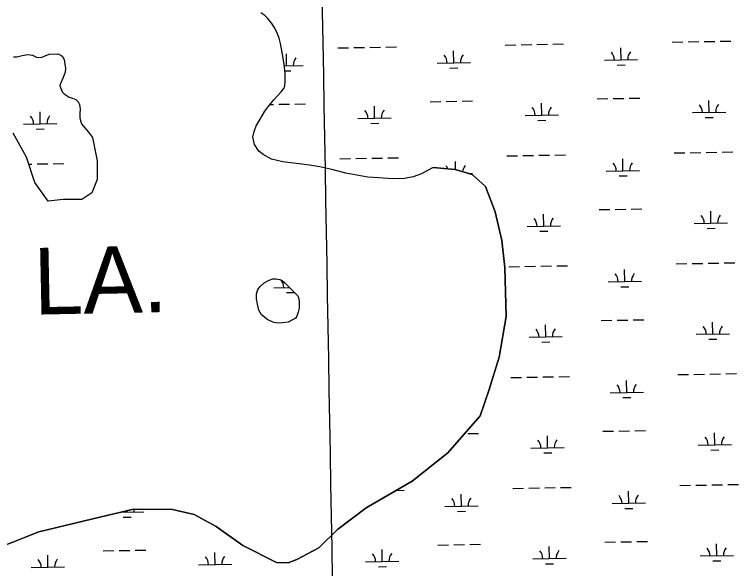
# Model space of a CAD drawing. Extents: x 3892998 to 3931244, y 278583 to 304547.
# Drawn here: x 3917313 to 3919486, y 298805 to 300467 of the extents above; entities that cross this region are included whole.
import ezdxf

# ---------------------------------------------------------------- set-up
doc = ezdxf.new("R2010")
doc.units = 0
for name, color, linetype in [('V-GRID-MAJR', 7, 'Continuous'), ('V-TOPO-GNAM-IDEN', 7, 'Continuous'), ('V-TOPO-SHOR', 7, 'Continuous'), ('V-WETL-SWMP', 7, 'Continuous')]:
    doc.layers.add(name, color=color, linetype=linetype)

msp = doc.modelspace()

# ---------------------------------------------------------------- linework, layer by layer
at = {"layer": 'V-GRID-MAJR'}
msp.add_spline([(3918519.216, 284383.145), (3918413.491, 290439.973), (3918307.7120000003, 296499.886), (3918201.934, 302559.792), (3918201.88, 302562.882)], degree=3, dxfattribs=at)
at = {"layer": 'V-TOPO-SHOR'}
for points in [[(3918570.412, 300008.11100000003), (3918552.9110000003, 299999.548), (3918534.8030000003, 299989.208), (3918509.971, 299980.115), (3918483.789, 299975.189), (3918448.3370000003, 299974.503), (3918406.176, 299976.846), (3918374.318, 299979.496), (3918307.485, 299991.16000000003), (3918265.399, 300002.016), (3918230.216, 300009.843), (3918198.577, 300014.867), (3918167.324, 300019.096), (3918142.199, 300022.08400000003), (3918119.2600000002, 300025.648), (3918084.47, 300033.076), (3918060.034, 300046.949), (3918047.055, 300057.556), (3918033.7600000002, 300077.27400000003), (3918028.796, 300098.903), (3918032.31, 300116.10000000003), (3918039.193, 300133.666), (3918050.256, 300153.57), (3918064.719, 300177.605), (3918076.344, 300193.744), (3918091.54, 300210.842), (3918113.529, 300234.81200000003), (3918121.74, 300245.239), (3918124.384, 300253.533), (3918126.282, 300266.982), (3918125.49, 300289.961), (3918122.367, 300318.303), (3918116.329, 300353.20900000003), (3918111.809, 300380.378), (3918107.394, 300396.653), (3918100.416, 300414.338), (3918092.429, 300429.655), (3918085.99, 300440.8), (3918074.04, 300455.755), (3918064.605, 300463.955), (3918053.1890000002, 300472.17100000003)], [(3917310.1890000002, 300340.018), (3917319.919, 300339.934), (3917336.6350000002, 300344.159), (3917353.345, 300347.786), (3917367.423, 300345.482), (3917379.481, 300339.422), (3917385.625, 300338.179), (3917395.562, 300339.28500000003), (3917405.329, 300343.371), (3917417.2830000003, 300348.23), (3917443.895, 300348.798), (3917452.798, 300344.947), (3917457.528, 300340.935), (3917462.812, 300331.957), (3917466.3570000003, 300305.517), (3917465.2660000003, 300294.01), (3917459.968, 300278.17), (3917452.486, 300262.548), (3917450.664, 300258.395), (3917449.623, 300252.84500000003), (3917456.0270000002, 300235.515), (3917462.728, 300229.69800000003), (3917477.931, 300219.641), (3917487.634, 300216.579), (3917497.722, 300212.32300000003), (3917504.219, 300205.714), (3917508.909, 300196.939), (3917510.381, 300183.424), (3917509.0810000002, 300170.726), (3917509.7630000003, 300157.617), (3917511.473, 300148.667), (3917514.772, 300139.703), (3917523.4110000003, 300128.31), (3917535.6040000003, 300114.705), (3917547.38, 300098.718)], [(3917547.38, 300098.718), (3917561.9560000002, 300027.729), (3917561.4790000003, 299972.052), (3917545.947, 299931.69), (3917515.403, 299911.703), (3917459.728, 299912.183), (3917414.129, 299907.511), (3917374.115, 299963.536), (3917349.46, 300039.677), (3917309.577, 300110.884)], [(3918570.412, 300008.11100000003), (3918636.169, 300002.485), (3918686.6520000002, 299986.867), (3918726.842, 299951.088), (3918756.558, 299874.905), (3918776.066, 299788.684), (3918785.4930000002, 299707.614), (3918789.296, 299560.787), (3918768.007, 299439.48600000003), (3918736.769, 299338.515), (3918710.808, 299262.811), (3918613.684, 299152.282), (3918506.653, 299067.14900000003), (3918369.298, 298987.339), (3918282.688, 298922.278), (3918226.534, 298867.08), (3918160.431, 298832.215), (3918135.0360000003, 298822.309), (3918099.605, 298822.612), (3917998.809, 298874.096), (3917918.304, 298930.468), (3917852.809, 298966.463), (3917787.14, 298982.212), (3917670.723, 298983.212), (3917548.988, 298953.886), (3917386.6720000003, 298914.784), (3917234.305, 298855.349)], [(3918148.057, 299550.928), (3918134.734, 299544.507), (3918118.275, 299541.878), (3918104.211, 299541.402), (3918091.356, 299543.297), (3918073.598, 299550.77400000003), (3918054.914, 299565.788), (3918046.72, 299580.116), (3918042.3200000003, 299598.175), (3918039.877, 299613.641), (3918039.421, 299629.487), (3918043.289, 299641.931), (3918050.494, 299650.78), (3918062.872, 299662.357), (3918078.187, 299670.146), (3918089.111, 299674.012), (3918098.225, 299674.529), (3918109.495, 299672.452), (3918116.989, 299668.82300000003), (3918125.049, 299662.021), (3918133.688, 299653.233), (3918141.339, 299645.05), (3918154.694, 299632.061), (3918163.921, 299622.675), (3918165.852, 299616.916), (3918167.548, 299606.803), (3918167.7830000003, 299588.18700000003), (3918166.7430000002, 299582.254), (3918164.691, 299573.955), (3918160.625, 299561.712), (3918156.417, 299555.808), (3918148.057, 299550.928)]]:
    msp.add_lwpolyline(points, dxfattribs=at)
at = {"layer": 'V-WETL-SWMP'}
for p, q in [((3918064.6040000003, 300463.954), (3918053.1890000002, 300472.17100000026)), ((3918074.039, 300455.754), (3918064.6040000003, 300463.954)), ((3918085.99, 300440.799), (3918074.039, 300455.754)), ((3918092.429, 300429.654), (3918085.99, 300440.799)), ((3918100.417, 300414.3380000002), (3918092.429, 300429.654)), ((3918107.394, 300396.6530000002), (3918100.417, 300414.3380000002)), ((3918111.809, 300380.377), (3918107.394, 300396.6530000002)), ((3918116.329, 300353.20900000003), (3918111.809, 300380.377)), ((3918785.654375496, 300375.7764404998), (3918817.649582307, 300376.33028264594)), ((3918833.647185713, 300376.6072037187), (3918865.642392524, 300377.1610458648)), ((3918881.639995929, 300377.4379669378), (3918913.63520274, 300377.99180908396)), ((3918929.6328061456, 300378.2687301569), (3918961.6280129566, 300378.82257230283)), ((3919287.487196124, 300384.46324686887), (3919319.482402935, 300385.017089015)), ((3919335.48000634, 300385.29401008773), (3919367.475213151, 300385.8478522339)), ((3919383.472816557, 300386.12477330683), (3919415.468023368, 300386.678615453)), ((3919431.465626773, 300386.955536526), (3919463.4608335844, 300387.5093786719)), ((3918122.366, 300318.304), (3918116.329, 300353.20900000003)), ((3918283.821554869, 300367.0896341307), (3918315.81676168, 300367.6434762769)), ((3918331.8143650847, 300367.9203973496), (3918363.8095718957, 300368.47423949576)), ((3918379.8071753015, 300368.75116056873), (3918411.8023821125, 300369.30500271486)), ((3918427.7999855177, 300369.58192378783), (3918459.795192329, 300370.1357659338)), ((3918631.96375196, 300322.3664295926), (3918631.340679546, 300358.3610372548)), ((3919133.796572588, 300331.0532359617), (3919133.1735001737, 300367.0478436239)), ((3918130.1309313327, 300313.67962322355), (3918129.507858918, 300349.67423088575)), ((3919083.804061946, 300330.18785760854), (3919183.7890832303, 300331.9186143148)), ((3918125.489, 300289.96), (3918122.366, 300318.304)), ((3918122.88933498, 300313.5542700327), (3918180.1234419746, 300314.54500157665)), ((3918581.9712413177, 300321.5010512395), (3918681.956262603, 300323.23180794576)), ((3919122.065443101, 300315.41685652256), (3919146.0618482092, 300315.83223813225)), ((3918124.5865718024, 300298.1503377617), (3918142.396206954, 300298.4586253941)), ((3918126.282, 300266.982), (3918125.489, 300289.96)), ((3918620.2326224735, 300306.7300501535), (3918644.2290275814, 300307.1454317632)), ((3918124.384, 300253.532), (3918126.282, 300266.982)), ((3918113.5300000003, 300234.813), (3918121.739, 300245.238)), ((3918121.739, 300245.238), (3918124.384, 300253.532)), ((3918091.541, 300210.842), (3918113.5300000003, 300234.813)), ((3918076.344, 300193.744), (3918091.541, 300210.842)), ((3918154.7173944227, 300198.6559260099), (3918186.7126012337, 300199.2097681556)), ((3918560.564594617, 300205.6812059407), (3918592.559801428, 300206.2350480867)), ((3918608.5574048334, 300206.5119691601), (3918640.552611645, 300207.0658113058)), ((3918656.5502150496, 300207.342732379), (3918688.5454218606, 300207.89657452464)), ((3918896.162029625, 300165.0534955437), (3918895.5389572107, 300201.0481032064)), ((3919062.3974152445, 300214.3680123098), (3919094.392622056, 300214.9218544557)), ((3919110.390225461, 300215.19877552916), (3919142.385432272, 300215.7526176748)), ((3919158.383035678, 300216.02953874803), (3919190.378242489, 300216.5833808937)), ((3919397.9948502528, 300173.74030191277), (3919397.3717778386, 300209.7349095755)), ((3918050.256, 300153.571), (3918064.72, 300177.606)), ((3918064.72, 300177.606), (3918076.344, 300193.744)), ((3918079.5533637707, 300197.35482462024), (3918090.7269808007, 300197.54824171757)), ((3918106.7245842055, 300197.825162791), (3918138.7197910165, 300198.3790049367)), ((3918394.3292089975, 300156.36668917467), (3918393.7061365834, 300192.36129683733)), ((3917390.6635677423, 300138.9930764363), (3917390.040495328, 300174.98768409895)), ((3918344.3366983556, 300155.50131082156), (3918444.3217196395, 300157.23206752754)), ((3918846.169518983, 300164.1881171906), (3918946.154540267, 300165.9188738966)), ((3919348.0023396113, 300172.87492355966), (3919447.9873608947, 300174.6056802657)), ((3919386.263720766, 300158.1039224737), (3919410.2601258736, 300158.5193040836)), ((3917340.6710571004, 300138.1276980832), (3917440.6560783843, 300139.85845478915)), ((3918032.31, 300116.10000000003), (3918039.194, 300133.665)), ((3918039.194, 300133.665), (3918050.256, 300153.571)), ((3918382.598079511, 300140.7303097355), (3918406.5944846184, 300141.14569134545)), ((3918884.430900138, 300149.4171161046), (3918908.4273052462, 300149.83249771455)), ((3917378.9324382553, 300123.3566969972), (3917402.928843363, 300123.7720786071)), ((3918028.796, 300098.90200000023), (3918032.31, 300116.10000000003)), ((3918033.759, 300077.27400000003), (3918028.796, 300098.90200000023)), ((3918047.056, 300057.556), (3918033.759, 300077.27400000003)), ((3918060.034, 300046.949), (3918047.056, 300057.556)), ((3918084.47, 300033.075), (3918060.034, 300046.949)), ((3919293.2449909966, 300051.8380773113), (3919325.2401978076, 300052.39191945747)), ((3919341.237801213, 300052.66884053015), (3919373.233008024, 300053.22268267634)), ((3919389.230611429, 300053.49960374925), (3919421.22581824, 300054.05344589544)), ((3919437.223421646, 300054.3303669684), (3919469.2186284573, 300054.8842091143)), ((3918119.259, 300025.647), (3918084.47, 300033.075)), ((3918142.2, 300022.08400000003), (3918119.259, 300025.64699999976)), ((3918289.579349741, 300034.46446457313), (3918321.574556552, 300035.0183067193)), ((3918337.5721599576, 300035.29522779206), (3918369.5673667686, 300035.8490699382)), ((3918385.564970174, 300036.12599101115), (3918417.560176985, 300036.6798331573)), ((3918433.55778039, 300036.95675423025), (3918465.5529872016, 300037.5105963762)), ((3918637.5081275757, 300002.07039263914), (3918637.0984744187, 300025.7358676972)), ((3918791.4121703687, 300043.15127094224), (3918823.4073771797, 300043.70511308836)), ((3918839.404980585, 300043.9820341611), (3918871.400187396, 300044.5358763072)), ((3918887.3977908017, 300044.8127973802), (3918919.3929976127, 300045.3666395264)), ((3918935.390601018, 300045.64356059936), (3918967.385807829, 300046.19740274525)), ((3919139.5543674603, 299998.4280664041), (3919138.931295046, 300034.4226740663)), ((3917356.378637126, 300018.310611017), (3917365.9017255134, 300018.4754571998)), ((3917381.8993289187, 300018.75237827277), (3917413.8945357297, 300019.30622041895)), ((3917429.8921391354, 300019.5831414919), (3917461.8873459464, 300020.1369836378)), ((3918167.324, 300019.09600000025), (3918142.2, 300022.08400000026)), ((3918198.576, 300014.86700000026), (3918167.324, 300019.09600000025)), ((3918230.217, 300009.843), (3918198.576, 300014.86700000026)), ((3918265.398, 300002.016), (3918230.217, 300009.843)), ((3918570.412, 300008.11100000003), (3918552.912, 299999.548)), ((3918636.168, 300002.485), (3918570.412, 300008.11100000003)), ((3918307.485, 299991.159), (3918265.398, 300002.016)), ((3918374.318, 299979.496), (3918307.485, 299991.159)), ((3918534.8030000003, 299989.208), (3918509.971, 299980.114)), ((3918552.912, 299999.548), (3918534.8030000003, 299989.208)), ((3918686.653, 299986.866), (3918636.168, 300002.485)), ((3918675.259077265, 299990.39104068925), (3918687.7140574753, 299990.6066383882)), ((3918726.841, 299951.088), (3918686.653, 299986.866)), ((3919089.5618568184, 299997.56268805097), (3919189.5468781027, 299999.29344475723)), ((3919127.8232379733, 299982.791686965), (3919151.8196430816, 299983.2070685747)), ((3918406.177, 299976.846), (3918374.318, 299979.49599999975)), ((3918448.3370000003, 299974.504), (3918406.177, 299976.846)), ((3918483.789, 299975.19000000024), (3918448.3370000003, 299974.504)), ((3918509.971, 299980.114), (3918483.789, 299975.18999999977)), ((3918756.558, 299874.904), (3918726.841, 299951.088)), ((3918776.065, 299788.685), (3918756.558, 299874.904)), ((3919068.1552101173, 299881.7428427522), (3919100.1504169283, 299882.29668489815)), ((3919116.148020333, 299882.5736059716), (3919148.1432271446, 299883.12744811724)), ((3919164.1408305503, 299883.40436919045), (3919196.1360373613, 299883.95821133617)), ((3919403.7526451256, 299841.11513235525), (3919403.129572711, 299877.1097400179)), ((3918901.9198244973, 299832.42832598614), (3918901.2967520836, 299868.4229336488)), ((3918851.927313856, 299831.56294763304), (3918951.9123351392, 299833.293704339)), ((3919353.760134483, 299840.2497540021), (3919453.7451557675, 299841.9805107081)), ((3918890.1886950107, 299816.79194654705), (3918914.1851001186, 299817.207328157)), ((3919392.0215156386, 299825.4787529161), (3919416.0179207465, 299825.894134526)), ((3918785.4930000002, 299707.61400000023), (3918776.065, 299788.685)), ((3919346.9955960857, 299720.0436709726), (3919378.9908028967, 299720.59751311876)), ((3919394.9884063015, 299720.87443419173), (3919426.9836131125, 299721.42827633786)), ((3919442.9812165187, 299721.70519741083), (3919474.976423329, 299722.2590395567)), ((3918789.295, 299560.78700000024), (3918785.4930000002, 299707.61400000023)), ((3918797.1699652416, 299710.52610138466), (3918829.1651720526, 299711.0799435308)), ((3918845.1627754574, 299711.3568646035), (3918877.1579822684, 299711.9107067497)), ((3918893.1555856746, 299712.1876278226), (3918925.150792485, 299712.7414699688)), ((3918941.1483958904, 299713.0183910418), (3918973.143602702, 299713.5722331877)), ((3919145.3121623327, 299665.80289684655), (3919144.6890899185, 299701.79750450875)), ((3919299.002785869, 299719.2129077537), (3919330.9979926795, 299719.7667498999)), ((3919095.319651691, 299664.93751849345), (3919195.3046729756, 299666.66827519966)), ((3918091.654010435, 299647.5639057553), (3918138.2342720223, 299648.3702175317)), ((3919133.581032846, 299650.1665174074), (3919157.577437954, 299650.5818990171)), ((3918129.9153915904, 299632.7929046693), (3918153.522254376, 299633.2015432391)), ((3918768.006, 299439.485), (3918789.295, 299560.78700000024)), ((3919073.9130049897, 299549.1176731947), (3919105.9082118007, 299549.67151534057)), ((3919121.9058152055, 299549.948436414), (3919153.901022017, 299550.50227855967)), ((3919169.8986254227, 299550.7791996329), (3919201.8938322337, 299551.3330417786)), ((3918907.6776193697, 299499.80315642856), (3918907.0545469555, 299535.7977640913)), ((3919409.5104399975, 299508.48996279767), (3919408.8873675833, 299544.48457046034)), ((3919359.5179293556, 299507.6245844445), (3919459.50295064, 299509.35534115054)), ((3918857.6851087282, 299498.93777807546), (3918957.6701300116, 299500.66853478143)), ((3918895.946489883, 299484.16677698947), (3918919.942894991, 299484.5821585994)), ((3919397.7793105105, 299492.8535833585), (3919421.775715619, 299493.26896496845)), ((3918736.768, 299338.51500000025), (3918768.006, 299439.485)), ((3918802.927760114, 299377.9009318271), (3918834.922966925, 299378.4547739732)), ((3918850.9205703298, 299378.73169504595), (3918882.9157771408, 299379.28553719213)), ((3918898.9133805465, 299379.56245826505), (3918930.9085873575, 299380.11630041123)), ((3918946.9061907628, 299380.3932214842), (3918978.901397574, 299380.9470636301)), ((3919304.760580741, 299386.58773819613), (3919336.755787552, 299387.1415803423)), ((3919352.753390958, 299387.418501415), (3919384.748597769, 299387.9723435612)), ((3919400.746201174, 299388.24926463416), (3919432.741407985, 299388.8031067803)), ((3919448.7390113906, 299389.08002785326), (3919480.7342182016, 299389.6338699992)), ((3919151.069957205, 299333.177727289), (3919150.446884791, 299369.1723349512)), ((3918710.808, 299262.81), (3918736.768, 299338.51500000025)), ((3919101.0774465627, 299332.31234893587), (3919201.062467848, 299334.0431056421)), ((3919139.3388277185, 299317.5413478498), (3919163.3352328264, 299317.9567294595)), ((3918613.684, 299152.283), (3918710.808, 299262.81)), ((3918673.8235996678, 299209.46722370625), (3918705.8188064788, 299210.0210658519)), ((3918913.4354142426, 299167.177986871), (3918912.8123418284, 299203.1725945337)), ((3919079.670799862, 299216.4925036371), (3919111.666006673, 299217.046345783)), ((3919127.6636100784, 299217.32326685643), (3919159.65881689, 299217.87710900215)), ((3919175.6564202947, 299218.1540300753), (3919207.6516271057, 299218.707872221)), ((3919415.26823487, 299175.8647932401), (3919414.6451624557, 299211.85940090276)), ((3918863.4429036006, 299166.3126085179), (3918963.4279248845, 299168.0433652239)), ((3919365.275724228, 299174.99941488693), (3919465.2607455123, 299176.73017159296)), ((3919403.537105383, 299160.22841380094), (3919427.5335104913, 299160.64379541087)), ((3918506.654, 299067.15), (3918613.684, 299152.283)), ((3918901.704284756, 299151.5416074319), (3918925.7006898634, 299151.9569890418)), ((3918369.298, 298987.33900000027), (3918506.654, 299067.15)), ((3918904.671175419, 299046.93728870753), (3918936.66638223, 299047.49113085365)), ((3918952.663985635, 299047.7680519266), (3918984.6591924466, 299048.3218940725)), ((3919310.5183756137, 299053.96256863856), (3919342.5135824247, 299054.51641078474)), ((3919358.51118583, 299054.7933318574), (3919390.506392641, 299055.3471740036)), ((3919406.5039960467, 299055.6240950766), (3919438.4992028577, 299056.1779372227)), ((3919454.496806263, 299056.4548582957), (3919486.492013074, 299057.0087004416)), ((3918458.57801416, 299039.21534475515), (3918482.826371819, 299039.6350877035)), ((3918654.99493145, 298991.86575136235), (3918654.3718590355, 299027.86035902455)), ((3918808.685554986, 299045.2757622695), (3918840.680761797, 299045.8296044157)), ((3918856.6783652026, 299046.1065254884), (3918888.6735720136, 299046.66036763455)), ((3919156.8277520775, 299000.5525577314), (3919156.2046796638, 299036.5471653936)), ((3917548.987, 298953.88600000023), (3917670.724, 298983.21200000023)), ((3917670.724, 298983.21200000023), (3917787.139, 298982.212)), ((3917787.139, 298982.212), (3917852.808, 298966.4630000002)), ((3918282.688, 298922.2780000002), (3918369.298, 298987.33900000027)), ((3918605.0024208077, 298991.0003730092), (3918704.9874420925, 298992.73112971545)), ((3919106.8352414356, 298999.6871793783), (3919206.8202627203, 299001.4179360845)), ((3919145.096622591, 298984.9161782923), (3919169.0930276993, 298985.33155990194)), ((3917633.225550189, 298974.17875998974), (3917701.3218008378, 298975.35751697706)), ((3917651.3292901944, 298974.49213862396), (3917651.259514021, 298978.5230762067)), ((3917852.808, 298966.4630000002), (3917918.3030000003, 298930.4680000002)), ((3918643.263801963, 298976.2293719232), (3918667.2602070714, 298976.6447535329)), ((3917386.6720000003, 298914.784), (3917548.987, 298953.88599999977)), ((3917639.598160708, 298958.85575918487), (3917663.594565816, 298959.2711407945)), ((3917918.3030000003, 298930.468), (3917998.809, 298874.096)), ((3918226.5330000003, 298867.079), (3918282.688, 298922.2780000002)), ((3917234.305, 298855.349), (3917386.6720000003, 298914.784)), ((3917998.809, 298874.09600000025), (3918099.605, 298822.61200000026)), ((3918583.595774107, 298875.1805277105), (3918615.590980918, 298875.73436985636)), ((3918631.588584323, 298876.0112909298), (3918663.5837911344, 298876.56513307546)), ((3918679.58139454, 298876.84205414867), (3918711.5766013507, 298877.3958962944)), ((3919085.428594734, 298883.8673340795), (3919117.4238015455, 298884.4211762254)), ((3919133.4214049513, 298884.69809729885), (3919165.4166117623, 298885.25193944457)), ((3919181.4142151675, 298885.5288605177), (3919213.4094219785, 298886.08270266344)), ((3919421.0260297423, 298843.2396236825), (3919420.4029573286, 298879.2342313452)), ((3917579.9301328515, 298857.8069149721), (3917611.9253396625, 298858.360757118)), ((3917627.922943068, 298858.6376781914), (3917659.9181498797, 298859.19152033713)), ((3917675.9157532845, 298859.4684414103), (3917707.9109600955, 298860.022283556)), ((3917915.5275678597, 298817.1792045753), (3917914.9044954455, 298853.173812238)), ((3918160.43, 298832.21400000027), (3918226.5330000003, 298867.079)), ((3918417.360388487, 298825.86601094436), (3918416.737316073, 298861.860618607)), ((3918919.193209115, 298834.55281731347), (3918918.5701367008, 298870.54742497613)), ((3917413.694747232, 298808.492398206), (3917413.071674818, 298844.4870058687)), ((3918135.035, 298822.308), (3918160.43, 298832.214)), ((3918869.200698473, 298833.6874389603), (3918969.1857197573, 298835.41819566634)), ((3919371.033519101, 298842.3742453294), (3919471.0185403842, 298844.1050020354)), ((3917363.7022365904, 298807.62701985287), (3917463.6872578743, 298809.3577765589)), ((3917865.535057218, 298816.3138262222), (3917965.5200785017, 298818.0445829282)), ((3918099.605, 298822.61200000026), (3918135.035, 298822.30800000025)), ((3918367.367877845, 298825.00063259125), (3918467.352899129, 298826.73138929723)), ((3918405.6292590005, 298810.22963150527), (3918429.6256641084, 298810.6450131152)), ((3918907.462079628, 298818.9164378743), (3918931.4584847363, 298819.33181948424)), ((3919409.2949002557, 298827.60324424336), (3919433.2913053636, 298828.0186258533))]:
    msp.add_line(p, q, dxfattribs=at)
for points in [[(3917310.19, 300340.017), (3917319.919, 300339.933), (3917336.634, 300344.158), (3917353.344, 300347.787), (3917367.4220000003, 300345.482), (3917379.4820000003, 300339.422), (3917385.626, 300338.178), (3917395.563, 300339.284), (3917405.328, 300343.37), (3917417.2830000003, 300348.231), (3917443.895, 300348.797), (3917452.7970000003, 300344.94800000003), (3917457.528, 300340.936), (3917462.812, 300331.956), (3917466.3570000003, 300305.517), (3917465.2660000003, 300294.01), (3917459.967, 300278.17100000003), (3917452.486, 300262.549), (3917450.664, 300258.395), (3917449.623, 300252.84500000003), (3917456.0270000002, 300235.515), (3917462.728, 300229.699), (3917477.931, 300219.641), (3917487.634, 300216.579), (3917497.723, 300212.32300000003), (3917504.219, 300205.715), (3917508.909, 300196.938), (3917510.382, 300183.424), (3917509.0810000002, 300170.727), (3917509.7630000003, 300157.616), (3917511.473, 300148.667), (3917514.772, 300139.703), (3917523.41, 300128.311), (3917535.6040000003, 300114.705), (3917547.38, 300098.719)], [(3917547.38, 300098.719), (3917561.9560000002, 300027.728), (3917561.478, 299972.051), (3917545.946, 299931.689), (3917515.403, 299911.704), (3917459.727, 299912.18200000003), (3917414.13, 299907.512), (3917374.116, 299963.536), (3917349.46, 300039.676), (3917309.576, 300110.884)]]:
    msp.add_lwpolyline(points, dxfattribs=at)
msp.add_lwpolyline([(3918148.057, 299550.928), (3918134.734, 299544.50800000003), (3918118.275, 299541.877), (3918104.211, 299541.403), (3918091.356, 299543.29600000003), (3918073.597, 299550.775), (3918054.914, 299565.788), (3918046.72, 299580.116), (3918042.3200000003, 299598.174), (3918039.878, 299613.641), (3918039.42, 299629.487), (3918043.29, 299641.93), (3918050.495, 299650.779), (3918062.872, 299662.357), (3918078.187, 299670.146), (3918089.111, 299674.013), (3918098.225, 299674.529), (3918109.495, 299672.452), (3918116.988, 299668.82300000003), (3918125.049, 299662.021), (3918133.687, 299653.233), (3918141.34, 299645.049), (3918154.694, 299632.06200000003), (3918163.921, 299622.676), (3918165.852, 299616.916), (3918167.5470000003, 299606.803), (3918167.7830000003, 299588.186), (3918166.742, 299582.254), (3918164.691, 299573.955), (3918160.625, 299561.712), (3918156.416, 299555.80700000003)], close=True, dxfattribs=at)
for centre, radius, start, end in [((3919078.5536934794, 300330.571847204), 35.24628790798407, 0.21988000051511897, 41.76353833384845), ((3919189.0230163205, 300332.4840888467), 35.246287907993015, 140.21987699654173, 181.76353532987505), ((3918185.357375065, 300315.11047610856), 35.246287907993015, 140.21987699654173, 181.76353532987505), ((3918576.7208728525, 300321.8850408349), 35.24628790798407, 0.21988000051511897, 41.76353833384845), ((3918687.1901956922, 300323.7972824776), 35.246287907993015, 140.21987699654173, 181.76353532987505), ((3918339.086329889, 300155.8853004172), 35.24628790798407, 0.21988000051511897, 41.76353833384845), ((3918449.5556527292, 300157.7975420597), 35.246287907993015, 140.21987699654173, 181.76353532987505), ((3918840.9191505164, 300164.57210678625), 35.24628790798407, 0.21988000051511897, 41.76353833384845), ((3918951.3884733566, 300166.4843484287), 35.246287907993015, 140.21987699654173, 181.76353532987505), ((3919342.751971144, 300173.2589131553), 35.24628790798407, 0.21988000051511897, 41.76353833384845), ((3919453.2212939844, 300175.1711547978), 35.246287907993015, 140.21987699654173, 181.76353532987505), ((3917335.420688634, 300138.5116876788), 35.24628790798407, 0.21988000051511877, 41.76353833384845), ((3917445.8900114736, 300140.4239293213), 35.246287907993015, 140.21987699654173, 181.76353532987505), ((3918582.478667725, 299989.2598712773), 35.24628790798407, 25.355415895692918, 41.76353833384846), ((3918692.947990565, 299991.17211292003), 35.246287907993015, 140.21987699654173, 172.56781665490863), ((3919084.3114883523, 299997.9466776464), 35.24628790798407, 0.21988000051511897, 41.76353833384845), ((3919194.7808111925, 299999.85891928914), 35.246287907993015, 140.21987699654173, 181.76353532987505), ((3918846.676945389, 299831.94693722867), 35.24628790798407, 0.21988000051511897, 41.76353833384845), ((3918957.1462682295, 299833.85917887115), 35.246287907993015, 140.21987699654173, 181.76353532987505), ((3919348.509766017, 299840.6337435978), 35.24628790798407, 0.21988000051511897, 41.76353833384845), ((3919458.979088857, 299842.5459852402), 35.246287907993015, 140.21987699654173, 181.76353532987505), ((3919090.069283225, 299665.32150808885), 35.24628790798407, 0.21988000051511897, 41.76353833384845), ((3919200.538606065, 299667.23374973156), 35.246287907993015, 140.21987699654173, 181.76353532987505), ((3918086.40364197, 299647.9478953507), 35.24628790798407, 0.21988000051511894, 39.83995651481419), ((3919354.2675608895, 299508.0085740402), 35.24628790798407, 0.21988000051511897, 41.76353833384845), ((3919464.736883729, 299509.9208156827), 35.246287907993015, 140.21987699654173, 181.76353532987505), ((3918852.434740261, 299499.3217676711), 35.24628790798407, 0.21988000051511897, 41.76353833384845), ((3918962.904063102, 299501.2340093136), 35.246287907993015, 140.21987699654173, 181.76353532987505), ((3919095.8270780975, 299332.69633853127), 35.24628790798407, 0.21988000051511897, 41.76353833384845), ((3919206.2964009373, 299334.608580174), 35.246287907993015, 140.21987699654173, 181.76353532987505), ((3919470.4946786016, 299177.2956461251), 35.246287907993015, 140.21987699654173, 181.76353532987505), ((3918858.192535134, 299166.6965981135), 35.24628790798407, 0.21988000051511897, 41.76353833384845), ((3918968.6618579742, 299168.608839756), 35.246287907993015, 140.21987699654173, 181.76353532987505), ((3919360.0253557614, 299175.3834044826), 35.24628790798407, 0.21988000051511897, 41.76353833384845), ((3918599.752052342, 298991.38436260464), 35.24628790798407, 0.21988000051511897, 41.76353833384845), ((3918710.2213751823, 298993.29660424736), 35.246287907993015, 140.21987699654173, 181.76353532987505), ((3919101.58487297, 299000.0711689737), 35.24628790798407, 0.21988000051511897, 41.76353833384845), ((3919212.05419581, 299001.9834106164), 35.246287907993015, 140.21987699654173, 181.76353532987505), ((3917706.555733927, 298975.92299150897), 35.246287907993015, 168.084178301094, 181.76353532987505), ((3918863.950330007, 298834.071428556), 35.24628790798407, 0.21988000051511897, 41.76353833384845), ((3918974.4196528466, 298835.9836701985), 35.246287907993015, 140.21987699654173, 181.76353532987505), ((3919365.783150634, 298842.75823492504), 35.24628790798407, 0.21988000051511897, 41.76353833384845), ((3919476.2524734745, 298844.6704765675), 35.246287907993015, 140.21987699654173, 181.76353532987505), ((3917358.451868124, 298808.01100944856), 35.24628790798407, 0.21988000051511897, 41.76353833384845), ((3917468.921190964, 298809.92325109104), 35.246287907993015, 140.21987699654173, 181.76353532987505), ((3917860.284688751, 298816.69781581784), 35.24628790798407, 0.21988000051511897, 41.76353833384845), ((3917970.754011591, 298818.6100574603), 35.246287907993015, 140.21987699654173, 181.76353532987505), ((3918362.1175093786, 298825.3846221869), 35.24628790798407, 0.21988000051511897, 41.76353833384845), ((3918472.5868322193, 298827.29686382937), 35.246287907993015, 140.21987699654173, 181.76353532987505)]:
    msp.add_arc(centre, radius, start, end, dxfattribs=at)

# ---------------------------------------------------------------- texts
at = {"layer": 'V-TOPO-GNAM-IDEN'}
msp.add_text('LA.', height=199.99959800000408, rotation=1.1584721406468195, dxfattribs=at).set_placement((3917372.4281576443, 299566.5191945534))

doc.saveas('drawing.dxf')
